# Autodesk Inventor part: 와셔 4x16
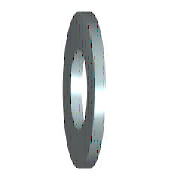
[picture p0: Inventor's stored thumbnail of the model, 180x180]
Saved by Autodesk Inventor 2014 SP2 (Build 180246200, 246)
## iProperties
IsCustomPart: 1
Created: 2012-02
Part Number: 와셔 4x16
Material: 강철, 연강
Description: 미터법 평면 와셔
Document SubType Name: Modeling
Standard: ANSI B18.22M
Designer: mduedu
Standard Revision: 1999
Standards Organization: ANSI
Language: ko-KR
Size Designation: 4 W
Categories: <MemberInstance><Categories><Category DisplayName="조임쇠" InternalName="e4da775c-781d-43d5-af7c-5136215cf5a6" Mnemonic="FSTN"><Category DisplayName="와셔" InternalN
Density: 1 g/cm^3
Appearance: 파란색 - 벽 페인트 - 광택
Author: mduedu
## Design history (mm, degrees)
sketch "스케치"
  geometry: C1 r 8 at (0, 0); C2 r 2.35 at (0, 0); 1 further point
  constraints: 2 centre point, 2 coincident
  dimensions: "d0" = 4.7 diameter of C2 (= SD1); "d1" = 16 diameter of C1 (= SD2)
extrude "본체" new body sketch "스케치" distance "d2" = 2.3 (= SD); taper "d3" = 0 deg
workaxis "Work Axis1"
workplane "Work Plane1"
body "Solid1"
other parameters: "SD1" = 4.7 [user parameter; used in 1 equation term], "SD2" = 16 [user parameter; used in 1 equation term], "SD" = 2.3 [user parameter; used in 1 equation term], "d4" = 0, "d5" = 0, "d6" = 0, "d7" = 0, "NND" = 4 [user parameter]
